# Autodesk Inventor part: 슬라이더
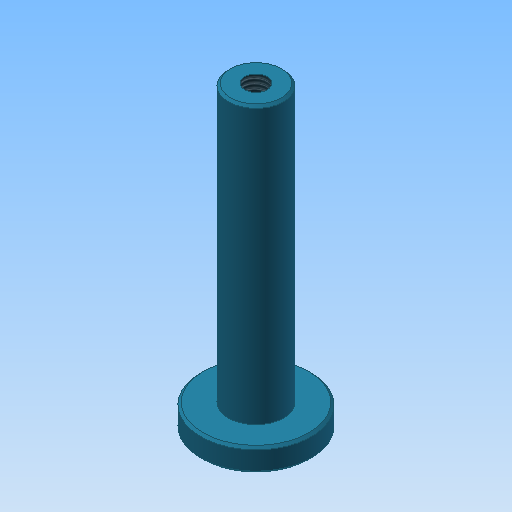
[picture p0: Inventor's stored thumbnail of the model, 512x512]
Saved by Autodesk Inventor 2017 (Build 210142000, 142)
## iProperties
Created: 2016-02
Part Number: 슬라이더
Material: 스테인리스강
Document SubType Name: Modeling
Designer: mduedu
Density: 8.08 g/cm^3
Appearance: 터키옥색
Mass: 71.0022 g
Surface Area: 36.7606 cm^2
Volume: 8.78741 cm^3
Author: mduedu
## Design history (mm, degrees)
sketch "스케치1"
  geometry: C1 r 12 at (0, 0); 1 further point
  constraints: 1 centre point, 1 coincident
  dimensions: "d0" = 24 diameter of C1
extrude "돌출1" new body sketch "스케치1" distance "d1" = 5; taper "d2" = 0 deg
sketch "스케치2"
  geometry: C1 r 6 at (0, 0); 1 further point
  constraints: 1 centre point, 1 coincident
  dimensions: "d3" = 12 diameter of C1
extrude "돌출2" join sketch "스케치2" distance "d4" = 60; taper "d5" = 0 deg
chamfer "모따기1" distance "d6" = 0.5; stored, may be unused: second distance "d7" = 2, angle "d8" = 45 deg
hole "구멍1" diameter "d11" = 4.917; stored, may be unused: countersink angle "d15" = 90 deg, drill point angle "d17" = 118 deg; dims "d9" = 10, "d10" = 10, "d12" = 10, "d13" = 4, "d14" = 2, "d16" = 12
chamfer "모따기2" distance "d18" = 0.5; stored, may be unused: second distance "d19" = 2, angle "d20" = 45 deg
node "솔리드1"
